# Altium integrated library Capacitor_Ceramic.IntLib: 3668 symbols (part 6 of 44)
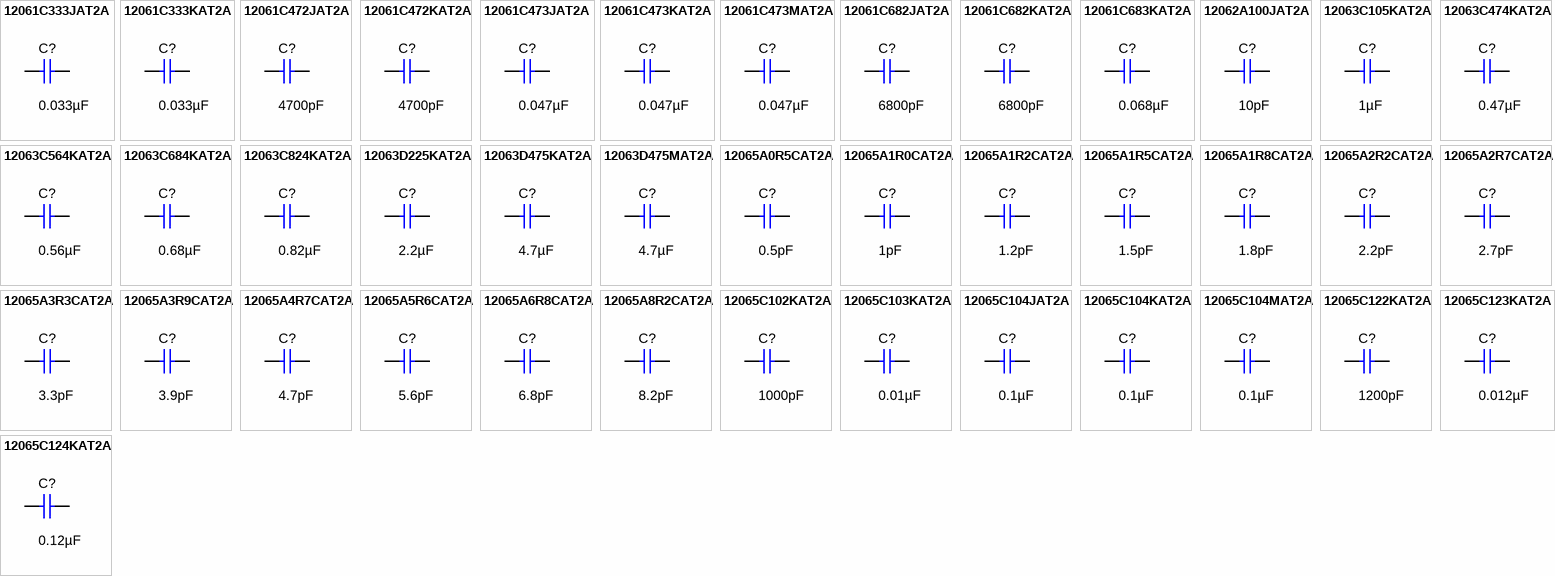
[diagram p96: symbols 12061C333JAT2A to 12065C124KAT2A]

## 12065C104KAT2A
designator C?  ValueDisplayed: 0.1µF  (hidden comment: 12065C104KAT2A)
CAP, CERM, 0.1 µF, 50 V,+/- 10%, X7R, 1206; Manufacturer: AVX; Polarized: N; CompType: Capacitor; Value: 0.1uF; U/M: EA; Cap_F: 0.0000001; Tolerance_%: 10; ESR_ohm: 0.037; Value1: 0.037 ohm; VDC_V: 50; Value2: 50V; TaMin_C: -55; TaMax_C: 125; Cap_Case: 1206; SizeArea_mm2: 5.12; SizeAreaWB_mm2: 10.92; SizeX_mm: 3.2; SizeY_mm: 1.6; SizeZ_mm: 1.35; AEC Category: Q200; Green_Lifecycle: Active; Green_REACh: Passed
signal-integrity model Cap
simulation model Cap
footprint 1206
footprint 1206M
footprint 1206L
pins: 1, 2

## 12065C104MAT2A
designator C?  ValueDisplayed: 0.1µF  (hidden comment: 12065C104MAT2A)
CAP, CERM, 0.1 µF, 50 V,+/- 20%, X7R, 1206; Manufacturer: AVX; Polarized: N; CompType: Capacitor; Value: 0.1uF; U/M: EA; Cap_F: 0.0000001; Tolerance_%: 20; ESR_ohm: 0.037; Value1: 0.037 ohm; VDC_V: 50; Value2: 50V; TaMin_C: -55; TaMax_C: 125; Cap_Case: 1206; SizeArea_mm2: 5.12; SizeAreaWB_mm2: 10.92; SizeX_mm: 3.2; SizeY_mm: 1.6; SizeZ_mm: 1.35; AEC Category: Q200; Green_Lifecycle: Active; Green_REACh: Passed
signal-integrity model Cap
simulation model Cap
footprint 1206
footprint 1206M
footprint 1206L
pins: 1, 2

## 12065C122KAT2A
designator C?  ValueDisplayed: 1200pF  (hidden comment: 12065C122KAT2A)
CAP, CERM, 1200 pF, 50 V,+/- 10%, X7R, 1206; Manufacturer: AVX; Polarized: N; CompType: Capacitor; Value: 1200pF; U/M: EA; Cap_F: 0.0000000012; Tolerance_%: 10; ESR_ohm: 0.385; Value1: 0.385 ohm; VDC_V: 50; Value2: 50V; TaMin_C: -55; TaMax_C: 125; Cap_Case: 1206; SizeArea_mm2: 5.12; SizeAreaWB_mm2: 10.92; SizeX_mm: 3.2; SizeY_mm: 1.6; SizeZ_mm: 1.35; AEC Category: Q200; Green_Lifecycle: Not Set; Green_REACh: Incomplete
signal-integrity model Cap
simulation model Cap
footprint 1206
footprint 1206M
footprint 1206L
pins: 1, 2

## 12065C123KAT2A
designator C?  ValueDisplayed: 0.012µF  (hidden comment: 12065C123KAT2A)
CAP, CERM, 0.012 µF, 50 V,+/- 10%, X7R, 1206; Manufacturer: AVX; Polarized: N; CompType: Capacitor; Value: 0.012uF; U/M: EA; Cap_F: 0.000000012; Tolerance_%: 10; ESR_ohm: 0.108; Value1: 0.108 ohm; VDC_V: 50; Value2: 50V; TaMin_C: -55; TaMax_C: 125; Cap_Case: 1206; SizeArea_mm2: 5.12; SizeAreaWB_mm2: 10.92; SizeX_mm: 3.2; SizeY_mm: 1.6; SizeZ_mm: 1.35; AEC Category: Q200; Green_Lifecycle: Not Set; Green_REACh: Incomplete
signal-integrity model Cap
simulation model Cap
footprint 1206
footprint 1206M
footprint 1206L
pins: 1, 2

## 12065C124KAT2A
designator C?  ValueDisplayed: 0.12µF  (hidden comment: 12065C124KAT2A)
CAP, CERM, 0.12 µF, 50 V,+/- 10%, X7R, 1206; Manufacturer: AVX; Polarized: N; CompType: Capacitor; Value: 0.12uF; U/M: EA; Cap_F: 0.00000012; Tolerance_%: 10; ESR_ohm: 0.034; Value1: 0.034 ohm; VDC_V: 50; Value2: 50V; TaMin_C: -55; TaMax_C: 125; Cap_Case: 1206; SizeArea_mm2: 5.12; SizeAreaWB_mm2: 10.92; SizeX_mm: 3.2; SizeY_mm: 1.6; SizeZ_mm: 1.35; AEC Category: Q200; Green_Lifecycle: Not Set; Green_REACh: Incomplete
signal-integrity model Cap
simulation model Cap
footprint 1206
footprint 1206M
footprint 1206L
pins: 1, 2

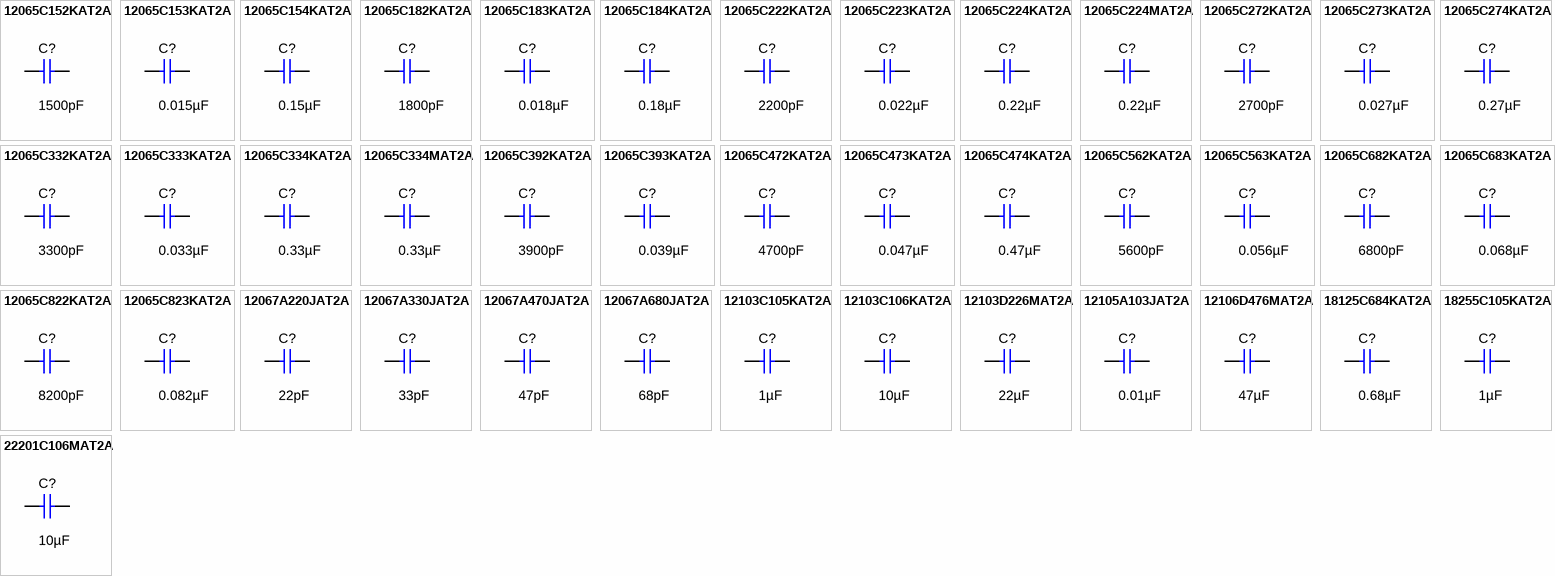
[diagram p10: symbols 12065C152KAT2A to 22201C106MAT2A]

## 12065C152KAT2A
designator C?  ValueDisplayed: 1500pF  (hidden comment: 12065C152KAT2A)
CAP, CERM, 1500 pF, 50 V,+/- 10%, X7R, 1206; Manufacturer: AVX; Polarized: N; CompType: Capacitor; Value: 1500pF; U/M: EA; Cap_F: 0.0000000015; Tolerance_%: 10; ESR_ohm: 0.338; Value1: 0.338 ohm; VDC_V: 50; Value2: 50V; TaMin_C: -55; TaMax_C: 125; Cap_Case: 1206; SizeArea_mm2: 5.12; SizeAreaWB_mm2: 10.92; SizeX_mm: 3.2; SizeY_mm: 1.6; SizeZ_mm: 1.35; AEC Category: Q200; Green_Lifecycle: Not Set; Green_REACh: Incomplete
signal-integrity model Cap
simulation model Cap
footprint 1206
footprint 1206M
footprint 1206L
pins: 1, 2

## 12065C153KAT2A
designator C?  ValueDisplayed: 0.015µF  (hidden comment: 12065C153KAT2A)
CAP, CERM, 0.015 µF, 50 V,+/- 10%, X7R, 1206; Manufacturer: AVX; Polarized: N; CompType: Capacitor; Value: 0.015uF; U/M: EA; Cap_F: 0.000000015; Tolerance_%: 10; ESR_ohm: 0.096; Value1: 0.096 ohm; VDC_V: 50; Value2: 50V; TaMin_C: -55; TaMax_C: 125; Cap_Case: 1206; SizeArea_mm2: 5.12; SizeAreaWB_mm2: 10.92; SizeX_mm: 3.2; SizeY_mm: 1.6; SizeZ_mm: 1.35; AEC Category: Q200; Green_Lifecycle: Not Set; Green_REACh: Incomplete
signal-integrity model Cap
simulation model Cap
footprint 1206
footprint 1206M
footprint 1206L
pins: 1, 2

## 12065C154KAT2A
designator C?  ValueDisplayed: 0.15µF  (hidden comment: 12065C154KAT2A)
CAP, CERM, 0.15 µF, 50 V,+/- 10%, X7R, 1206; Manufacturer: AVX; Polarized: N; CompType: Capacitor; Value: 0.15uF; U/M: EA; Cap_F: 0.00000015; Tolerance_%: 10; ESR_ohm: 0.03; Value1: 0.03 ohm; VDC_V: 50; Value2: 50V; TaMin_C: -55; TaMax_C: 125; Cap_Case: 1206; SizeArea_mm2: 5.12; SizeAreaWB_mm2: 10.92; SizeX_mm: 3.2; SizeY_mm: 1.6; SizeZ_mm: 1.35; AEC Category: Q200; Green_Lifecycle: Not Set; Green_REACh: Incomplete
signal-integrity model Cap
simulation model Cap
footprint 1206
footprint 1206M
footprint 1206L
pins: 1, 2

## 12065C182KAT2A
designator C?  ValueDisplayed: 1800pF  (hidden comment: 12065C182KAT2A)
CAP, CERM, 1800 pF, 50 V,+/- 10%, X7R, 1206; Manufacturer: AVX; Polarized: N; CompType: Capacitor; Value: 1800pF; U/M: EA; Cap_F: 0.0000000018; Tolerance_%: 10; ESR_ohm: 0.305; Value1: 0.305 ohm; VDC_V: 50; Value2: 50V; TaMin_C: -55; TaMax_C: 125; Cap_Case: 1206; SizeArea_mm2: 5.12; SizeAreaWB_mm2: 10.92; SizeX_mm: 3.2; SizeY_mm: 1.6; SizeZ_mm: 1.35; AEC Category: Q200; Green_Lifecycle: Not Set; Green_REACh: Incomplete
signal-integrity model Cap
simulation model Cap
footprint 1206
footprint 1206M
footprint 1206L
pins: 1, 2

## 12065C183KAT2A
designator C?  ValueDisplayed: 0.018µF  (hidden comment: 12065C183KAT2A)
CAP, CERM, 0.018 µF, 50 V,+/- 10%, X7R, 1206; Manufacturer: AVX; Polarized: N; CompType: Capacitor; Value: 0.018uF; U/M: EA; Cap_F: 0.000000018; Tolerance_%: 10; ESR_ohm: 0.087; Value1: 0.087 ohm; VDC_V: 50; Value2: 50V; TaMin_C: -55; TaMax_C: 125; Cap_Case: 1206; SizeArea_mm2: 5.12; SizeAreaWB_mm2: 10.92; SizeX_mm: 3.2; SizeY_mm: 1.6; SizeZ_mm: 1.35; AEC Category: Q200; Green_Lifecycle: Not Set; Green_REACh: Incomplete
signal-integrity model Cap
simulation model Cap
footprint 1206
footprint 1206M
footprint 1206L
pins: 1, 2

## 12065C184KAT2A
designator C?  ValueDisplayed: 0.18µF  (hidden comment: 12065C184KAT2A)
CAP, CERM, 0.18 µF, 50 V,+/- 10%, X7R, 1206; Manufacturer: AVX; Polarized: N; CompType: Capacitor; Value: 0.18uF; U/M: EA; Cap_F: 0.00000018; Tolerance_%: 10; ESR_ohm: 0.028; Value1: 0.028 ohm; VDC_V: 50; Value2: 50V; TaMin_C: -55; TaMax_C: 125; Cap_Case: 1206; SizeArea_mm2: 5.12; SizeAreaWB_mm2: 10.92; SizeX_mm: 3.2; SizeY_mm: 1.6; SizeZ_mm: 1.35; AEC Category: Q200; Green_Lifecycle: Not Set; Green_REACh: Incomplete
signal-integrity model Cap
simulation model Cap
footprint 1206
footprint 1206M
footprint 1206L
pins: 1, 2

## 12065C222KAT2A
designator C?  ValueDisplayed: 2200pF  (hidden comment: 12065C222KAT2A)
CAP, CERM, 2200 pF, 50 V,+/- 10%, X7R, 1206; Manufacturer: AVX; Polarized: N; CompType: Capacitor; Value: 2200pF; U/M: EA; Cap_F: 0.0000000022; Tolerance_%: 10; ESR_ohm: 0.272; Value1: 0.272 ohm; VDC_V: 50; Value2: 50V; TaMin_C: -55; TaMax_C: 125; Cap_Case: 1206; SizeArea_mm2: 5.12; SizeAreaWB_mm2: 10.92; SizeX_mm: 3.2; SizeY_mm: 1.6; SizeZ_mm: 1.35; AEC Category: Q200; Green_Lifecycle: Not Set; Green_REACh: Incomplete
signal-integrity model Cap
simulation model Cap
footprint 1206
footprint 1206M
footprint 1206L
pins: 1, 2

## 12065C223KAT2A
designator C?  ValueDisplayed: 0.022µF  (hidden comment: 12065C223KAT2A)
CAP, CERM, 0.022 µF, 50 V,+/- 10%, X7R, 1206; Manufacturer: AVX; Polarized: N; CompType: Capacitor; Value: 0.022uF; U/M: EA; Cap_F: 0.000000022; Tolerance_%: 10; ESR_ohm: 0.079; Value1: 0.079 ohm; VDC_V: 50; Value2: 50V; TaMin_C: -55; TaMax_C: 125; Cap_Case: 1206; SizeArea_mm2: 5.12; SizeAreaWB_mm2: 10.92; SizeX_mm: 3.2; SizeY_mm: 1.6; SizeZ_mm: 1.35; AEC Category: Q200; Green_Lifecycle: Not Set; Green_REACh: Incomplete
signal-integrity model Cap
simulation model Cap
footprint 1206
footprint 1206M
footprint 1206L
pins: 1, 2

## 12065C224KAT2A
designator C?  ValueDisplayed: 0.22µF  (hidden comment: 12065C224KAT2A)
CAP, CERM, 0.22 µF, 50 V,+/- 10%, X7R, 1206; Manufacturer: AVX; Polarized: N; CompType: Capacitor; Value: 0.22uF; U/M: EA; Cap_F: 0.00000022; Tolerance_%: 10; ESR_ohm: 0.026; Value1: 0.026 ohm; VDC_V: 50; Value2: 50V; TaMin_C: -55; TaMax_C: 125; Cap_Case: 1206; SizeArea_mm2: 5.12; SizeAreaWB_mm2: 10.92; SizeX_mm: 3.2; SizeY_mm: 1.6; SizeZ_mm: 1.35; AEC Category: Q200; Green_Lifecycle: Not Set; Green_REACh: Incomplete
signal-integrity model Cap
simulation model Cap
footprint 1206
footprint 1206M
footprint 1206L
pins: 1, 2

## 12065C224MAT2A
designator C?  ValueDisplayed: 0.22µF  (hidden comment: 12065C224MAT2A)
CAP, CERM, 0.22 µF, 50 V,+/- 20%, X7R, 1206; Manufacturer: AVX; Polarized: N; CompType: Capacitor; Value: 0.22uF; U/M: EA; Cap_F: 0.00000022; Tolerance_%: 20; ESR_ohm: 0.026; Value1: 0.026 ohm; VDC_V: 50; Value2: 50V; TaMin_C: -55; TaMax_C: 125; Cap_Case: 1206; SizeArea_mm2: 5.12; SizeAreaWB_mm2: 10.92; SizeX_mm: 3.2; SizeY_mm: 1.6; SizeZ_mm: 1.35; AEC Category: Q200; Green_Lifecycle: Not Set; Green_REACh: Incomplete
signal-integrity model Cap
simulation model Cap
footprint 1206
footprint 1206M
footprint 1206L
pins: 1, 2

## 12065C272KAT2A
designator C?  ValueDisplayed: 2700pF  (hidden comment: 12065C272KAT2A)
CAP, CERM, 2700 pF, 50 V,+/- 10%, X7R, 1206; Manufacturer: AVX; Polarized: N; CompType: Capacitor; Value: 2700pF; U/M: EA; Cap_F: 0.0000000027; Tolerance_%: 10; ESR_ohm: 0.242; Value1: 0.242 ohm; VDC_V: 50; Value2: 50V; TaMin_C: -55; TaMax_C: 125; Cap_Case: 1206; SizeArea_mm2: 5.12; SizeAreaWB_mm2: 10.92; SizeX_mm: 3.2; SizeY_mm: 1.6; SizeZ_mm: 1.35; AEC Category: Q200; Green_Lifecycle: Not Set; Green_REACh: Incomplete
signal-integrity model Cap
simulation model Cap
footprint 1206
footprint 1206M
footprint 1206L
pins: 1, 2

## 12065C273KAT2A
designator C?  ValueDisplayed: 0.027µF  (hidden comment: 12065C273KAT2A)
CAP, CERM, 0.027 µF, 50 V,+/- 10%, X7R, 1206; Manufacturer: AVX; Polarized: N; CompType: Capacitor; Value: 0.027uF; U/M: EA; Cap_F: 0.000000027; Tolerance_%: 10; ESR_ohm: 0.071; Value1: 0.071 ohm; VDC_V: 50; Value2: 50V; TaMin_C: -55; TaMax_C: 125; Cap_Case: 1206; SizeArea_mm2: 5.12; SizeAreaWB_mm2: 10.92; SizeX_mm: 3.2; SizeY_mm: 1.6; SizeZ_mm: 1.35; AEC Category: Q200; Green_Lifecycle: Not Set; Green_REACh: Incomplete
signal-integrity model Cap
simulation model Cap
footprint 1206
footprint 1206M
footprint 1206L
pins: 1, 2

## 12065C274KAT2A
designator C?  ValueDisplayed: 0.27µF  (hidden comment: 12065C274KAT2A)
CAP, CERM, 0.27 µF, 50 V,+/- 10%, X7R, 1206; Manufacturer: AVX; Polarized: N; CompType: Capacitor; Value: 0.27uF; U/M: EA; Cap_F: 0.00000027; Tolerance_%: 10; ESR_ohm: 0.023; Value1: 0.023 ohm; VDC_V: 50; Value2: 50V; TaMin_C: -55; TaMax_C: 125; Cap_Case: 1206; SizeArea_mm2: 5.12; SizeAreaWB_mm2: 10.92; SizeX_mm: 3.2; SizeY_mm: 1.6; SizeZ_mm: 1.35; AEC Category: Q200; Green_Lifecycle: Not Set; Green_REACh: Incomplete
signal-integrity model Cap
simulation model Cap
footprint 1206
footprint 1206M
footprint 1206L
pins: 1, 2

## 12065C332KAT2A
designator C?  ValueDisplayed: 3300pF  (hidden comment: 12065C332KAT2A)
CAP, CERM, 3300 pF, 50 V,+/- 10%, X7R, 1206; Manufacturer: AVX; Polarized: N; CompType: Capacitor; Value: 3300pF; U/M: EA; Cap_F: 0.0000000033; Tolerance_%: 10; ESR_ohm: 0.216; Value1: 0.216 ohm; VDC_V: 50; Value2: 50V; TaMin_C: -55; TaMax_C: 125; Cap_Case: 1206; SizeArea_mm2: 5.12; SizeAreaWB_mm2: 10.92; SizeX_mm: 3.2; SizeY_mm: 1.6; SizeZ_mm: 1.35; AEC Category: Q200; Green_Lifecycle: Not Set; Green_REACh: Incomplete
signal-integrity model Cap
simulation model Cap
footprint 1206
footprint 1206M
footprint 1206L
pins: 1, 2

## 12065C333KAT2A
designator C?  ValueDisplayed: 0.033µF  (hidden comment: 12065C333KAT2A)
CAP, CERM, 0.033 µF, 50 V,+/- 10%, X7R, 1206; Manufacturer: AVX; Polarized: N; CompType: Capacitor; Value: 0.033uF; U/M: EA; Cap_F: 0.000000033; Tolerance_%: 10; ESR_ohm: 0.064; Value1: 0.064 ohm; VDC_V: 50; Value2: 50V; TaMin_C: -55; TaMax_C: 125; Cap_Case: 1206; SizeArea_mm2: 5.12; SizeAreaWB_mm2: 10.92; SizeX_mm: 3.2; SizeY_mm: 1.6; SizeZ_mm: 1.35; AEC Category: Q200; Green_Lifecycle: Not Set; Green_REACh: Incomplete
signal-integrity model Cap
simulation model Cap
footprint 1206
footprint 1206M
footprint 1206L
pins: 1, 2

## 12065C334KAT2A
designator C?  ValueDisplayed: 0.33µF  (hidden comment: 12065C334KAT2A)
CAP, CERM, 0.33 µF, 50 V,+/- 10%, X7R, 1206; Manufacturer: AVX; Polarized: N; CompType: Capacitor; Value: 0.33uF; U/M: EA; Cap_F: 0.00000033; Tolerance_%: 10; ESR_ohm: 0.021; Value1: 0.021 ohm; VDC_V: 50; Value2: 50V; TaMin_C: -55; TaMax_C: 125; Cap_Case: 1206; SizeArea_mm2: 5.12; SizeAreaWB_mm2: 10.92; SizeX_mm: 3.2; SizeY_mm: 1.6; SizeZ_mm: 1.35; AEC Category: Q200; Green_Lifecycle: Not Set; Green_REACh: Incomplete
signal-integrity model Cap
simulation model Cap
footprint 1206
footprint 1206M
footprint 1206L
pins: 1, 2

## 12065C334MAT2A
designator C?  ValueDisplayed: 0.33µF  (hidden comment: 12065C334MAT2A)
CAP, CERM, 0.33 µF, 50 V,+/- 20%, X7R, 1206; Manufacturer: AVX; Polarized: N; CompType: Capacitor; Value: 0.33uF; U/M: EA; Cap_F: 0.00000033; Tolerance_%: 20; ESR_ohm: 0.021; Value1: 0.021 ohm; VDC_V: 50; Value2: 50V; TaMin_C: -55; TaMax_C: 125; Cap_Case: 1206; SizeArea_mm2: 5.12; SizeAreaWB_mm2: 10.92; SizeX_mm: 3.2; SizeY_mm: 1.6; SizeZ_mm: 1.35; AEC Category: Q200; Green_Lifecycle: Not Set; Green_REACh: Incomplete
signal-integrity model Cap
simulation model Cap
footprint 1206
footprint 1206M
footprint 1206L
pins: 1, 2

## 12065C392KAT2A
designator C?  ValueDisplayed: 3900pF  (hidden comment: 12065C392KAT2A)
CAP, CERM, 3900 pF, 50 V,+/- 10%, X7R, 1206; Manufacturer: AVX; Polarized: N; CompType: Capacitor; Value: 3900pF; U/M: EA; Cap_F: 0.0000000039; Tolerance_%: 10; ESR_ohm: 0.196; Value1: 0.196 ohm; VDC_V: 50; Value2: 50V; TaMin_C: -55; TaMax_C: 125; Cap_Case: 1206; SizeArea_mm2: 5.12; SizeAreaWB_mm2: 10.92; SizeX_mm: 3.2; SizeY_mm: 1.6; SizeZ_mm: 1.35; AEC Category: Q200; Green_Lifecycle: Not Set; Green_REACh: Incomplete
signal-integrity model Cap
simulation model Cap
footprint 1206
footprint 1206M
footprint 1206L
pins: 1, 2

## 12065C393KAT2A
designator C?  ValueDisplayed: 0.039µF  (hidden comment: 12065C393KAT2A)
CAP, CERM, 0.039 µF, 50 V,+/- 10%, X7R, 1206; Manufacturer: AVX; Polarized: N; CompType: Capacitor; Value: 0.039uF; U/M: EA; Cap_F: 0.000000039; Tolerance_%: 10; ESR_ohm: 0.059; Value1: 0.059 ohm; VDC_V: 50; Value2: 50V; TaMin_C: -55; TaMax_C: 125; Cap_Case: 1206; SizeArea_mm2: 5.12; SizeAreaWB_mm2: 10.92; SizeX_mm: 3.2; SizeY_mm: 1.6; SizeZ_mm: 1.35; AEC Category: Q200; Green_Lifecycle: Not Set; Green_REACh: Incomplete
signal-integrity model Cap
simulation model Cap
footprint 1206
footprint 1206M
footprint 1206L
pins: 1, 2

## 12065C472KAT2A
designator C?  ValueDisplayed: 4700pF  (hidden comment: 12065C472KAT2A)
CAP, CERM, 4700 pF, 50 V,+/- 10%, X7R, 1206; Manufacturer: AVX; Polarized: N; CompType: Capacitor; Value: 4700pF; U/M: EA; Cap_F: 0.0000000047; Tolerance_%: 10; ESR_ohm: 0.178; Value1: 0.178 ohm; VDC_V: 50; Value2: 50V; TaMin_C: -55; TaMax_C: 125; Cap_Case: 1206; SizeArea_mm2: 5.12; SizeAreaWB_mm2: 10.92; SizeX_mm: 3.2; SizeY_mm: 1.6; SizeZ_mm: 1.35; AEC Category: Q200; Green_Lifecycle: Not Set; Green_REACh: Incomplete
signal-integrity model Cap
simulation model Cap
footprint 1206
footprint 1206M
footprint 1206L
pins: 1, 2

## 12065C473KAT2A
designator C?  ValueDisplayed: 0.047µF  (hidden comment: 12065C473KAT2A)
CAP, CERM, 0.047 µF, 50 V,+/- 10%, X7R, 1206; Manufacturer: AVX; Polarized: N; CompType: Capacitor; Value: 0.047uF; U/M: EA; Cap_F: 0.000000047; Tolerance_%: 10; ESR_ohm: 0.054; Value1: 0.054 ohm; VDC_V: 50; Value2: 50V; TaMin_C: -55; TaMax_C: 125; Cap_Case: 1206; SizeArea_mm2: 5.12; SizeAreaWB_mm2: 10.92; SizeX_mm: 3.2; SizeY_mm: 1.6; SizeZ_mm: 1.35; AEC Category: Q200; Green_Lifecycle: Not Set; Green_REACh: Incomplete
signal-integrity model Cap
simulation model Cap
footprint 1206
footprint 1206M
footprint 1206L
pins: 1, 2

## 12065C474KAT2A
designator C?  ValueDisplayed: 0.47µF  (hidden comment: 12065C474KAT2A)
CAP, CERM, 0.47 µF, 50 V,+/- 10%, X7R, 1206; Manufacturer: AVX; Polarized: N; CompType: Capacitor; Value: 0.47uF; U/M: EA; Cap_F: 0.00000047; Tolerance_%: 10; ESR_ohm: 0.018; Value1: 0.018 ohm; VDC_V: 50; Value2: 50V; TaMin_C: -55; TaMax_C: 125; Cap_Case: 1206; SizeArea_mm2: 5.12; SizeAreaWB_mm2: 10.92; SizeX_mm: 3.2; SizeY_mm: 1.6; SizeZ_mm: 1.35; AEC Category: Q200; Green_Lifecycle: Active; Green_REACh: Passed
signal-integrity model Cap
simulation model Cap
footprint 1206
footprint 1206M
footprint 1206L
pins: 1, 2

## 12065C562KAT2A
designator C?  ValueDisplayed: 5600pF  (hidden comment: 12065C562KAT2A)
CAP, CERM, 5600 pF, 50 V,+/- 10%, X7R, 1206; Manufacturer: AVX; Polarized: N; CompType: Capacitor; Value: 5600pF; U/M: EA; Cap_F: 0.0000000056; Tolerance_%: 10; ESR_ohm: 0.162; Value1: 0.162 ohm; VDC_V: 50; Value2: 50V; TaMin_C: -55; TaMax_C: 125; Cap_Case: 1206; SizeArea_mm2: 5.12; SizeAreaWB_mm2: 10.92; SizeX_mm: 3.2; SizeY_mm: 1.6; SizeZ_mm: 1.35; AEC Category: Q200; Green_Lifecycle: Not Set; Green_REACh: Incomplete
signal-integrity model Cap
simulation model Cap
footprint 1206
footprint 1206M
footprint 1206L
pins: 1, 2

## 12065C563KAT2A
designator C?  ValueDisplayed: 0.056µF  (hidden comment: 12065C563KAT2A)
CAP, CERM, 0.056 µF, 50 V,+/- 10%, X7R, 1206; Manufacturer: AVX; Polarized: N; CompType: Capacitor; Value: 0.056uF; U/M: EA; Cap_F: 0.000000056; Tolerance_%: 10; ESR_ohm: 0.049; Value1: 0.049 ohm; VDC_V: 50; Value2: 50V; TaMin_C: -55; TaMax_C: 125; Cap_Case: 1206; SizeArea_mm2: 5.12; SizeAreaWB_mm2: 10.92; SizeX_mm: 3.2; SizeY_mm: 1.6; SizeZ_mm: 1.35; AEC Category: Q200; Green_Lifecycle: Not Set; Green_REACh: Incomplete
signal-integrity model Cap
simulation model Cap
footprint 1206
footprint 1206M
footprint 1206L
pins: 1, 2

## 12065C682KAT2A
designator C?  ValueDisplayed: 6800pF  (hidden comment: 12065C682KAT2A)
CAP, CERM, 6800 pF, 50 V,+/- 10%, X7R, 1206; Manufacturer: AVX; Polarized: N; CompType: Capacitor; Value: 6800pF; U/M: EA; Cap_F: 0.0000000068; Tolerance_%: 10; ESR_ohm: 0.146; Value1: 0.146 ohm; VDC_V: 50; Value2: 50V; TaMin_C: -55; TaMax_C: 125; Cap_Case: 1206; SizeArea_mm2: 5.12; SizeAreaWB_mm2: 10.92; SizeX_mm: 3.2; SizeY_mm: 1.6; SizeZ_mm: 1.35; AEC Category: Q200; Green_Lifecycle: Not Set; Green_REACh: Incomplete
signal-integrity model Cap
simulation model Cap
footprint 1206
footprint 1206M
footprint 1206L
pins: 1, 2

## 12065C683KAT2A
designator C?  ValueDisplayed: 0.068µF  (hidden comment: 12065C683KAT2A)
CAP, CERM, 0.068 µF, 50 V,+/- 10%, X7R, 1206; Manufacturer: AVX; Polarized: N; CompType: Capacitor; Value: 0.068uF; U/M: EA; Cap_F: 0.000000068; Tolerance_%: 10; ESR_ohm: 0.045; Value1: 0.045 ohm; VDC_V: 50; Value2: 50V; TaMin_C: -55; TaMax_C: 125; Cap_Case: 1206; SizeArea_mm2: 5.12; SizeAreaWB_mm2: 10.92; SizeX_mm: 3.2; SizeY_mm: 1.6; SizeZ_mm: 1.35; AEC Category: Q200; Green_Lifecycle: Not Set; Green_REACh: Incomplete
signal-integrity model Cap
simulation model Cap
footprint 1206
footprint 1206M
footprint 1206L
pins: 1, 2

## 12065C822KAT2A
designator C?  ValueDisplayed: 8200pF  (hidden comment: 12065C822KAT2A)
CAP, CERM, 8200 pF, 50 V,+/- 10%, X7R, 1206; Manufacturer: AVX; Polarized: N; CompType: Capacitor; Value: 8200pF; U/M: EA; Cap_F: 0.0000000082; Tolerance_%: 10; ESR_ohm: 0.132; Value1: 0.132 ohm; VDC_V: 50; Value2: 50V; TaMin_C: -55; TaMax_C: 125; Cap_Case: 1206; SizeArea_mm2: 5.12; SizeAreaWB_mm2: 10.92; SizeX_mm: 3.2; SizeY_mm: 1.6; SizeZ_mm: 1.35; AEC Category: Q200; Green_Lifecycle: Not Set; Green_REACh: Incomplete
signal-integrity model Cap
simulation model Cap
footprint 1206
footprint 1206M
footprint 1206L
pins: 1, 2

## 12065C823KAT2A
designator C?  ValueDisplayed: 0.082µF  (hidden comment: 12065C823KAT2A)
CAP, CERM, 0.082 µF, 50 V,+/- 10%, X7R, 1206; Manufacturer: AVX; Polarized: N; CompType: Capacitor; Value: 0.082uF; U/M: EA; Cap_F: 0.000000082; Tolerance_%: 10; ESR_ohm: 0.041; Value1: 0.041 ohm; VDC_V: 50; Value2: 50V; TaMin_C: -55; TaMax_C: 125; Cap_Case: 1206; SizeArea_mm2: 5.12; SizeAreaWB_mm2: 10.92; SizeX_mm: 3.2; SizeY_mm: 1.6; SizeZ_mm: 1.35; AEC Category: Q200; Green_Lifecycle: Not Set; Green_REACh: Incomplete
signal-integrity model Cap
simulation model Cap
footprint 1206
footprint 1206M
footprint 1206L
pins: 1, 2

## 12067A220JAT2A
designator C?  ValueDisplayed: 22pF  (hidden comment: 12067A220JAT2A)
CAP, CERM, 22 pF, 500 V,+/- 5%, C0G/NP0, 1206; Manufacturer: AVX; Polarized: N; CompType: Capacitor; Value: 22pF; U/M: EA; Cap_F: 0.000000000022; Tolerance_%: 5; VDC_V: 500; Value2: 500V; TaMin_C: -55; TaMax_C: 125; Cap_Case: 1206; SizeArea_mm2: 5.12; SizeAreaWB_mm2: 10.92; SizeX_mm: 3.2; SizeY_mm: 1.6; SizeZ_mm: 1.35; AEC Category: Q200; Green_Lifecycle: Not Set; Green_REACh: Incomplete
signal-integrity model Cap
simulation model Cap
footprint 1206
footprint 1206M
footprint 1206L
pins: 1, 2

## 12067A330JAT2A
designator C?  ValueDisplayed: 33pF  (hidden comment: 12067A330JAT2A)
CAP, CERM, 33 pF, 500 V,+/- 5%, C0G/NP0, 1206; Manufacturer: AVX; Polarized: N; CompType: Capacitor; Value: 33pF; U/M: EA; Cap_F: 0.000000000033; Tolerance_%: 5; VDC_V: 500; Value2: 500V; TaMin_C: -55; TaMax_C: 125; Cap_Case: 1206; SizeArea_mm2: 5.12; SizeAreaWB_mm2: 10.92; SizeX_mm: 3.2; SizeY_mm: 1.6; SizeZ_mm: 1.35; AEC Category: Q200; Green_Lifecycle: Not Set; Green_REACh: Incomplete
signal-integrity model Cap
simulation model Cap
footprint 1206
footprint 1206M
footprint 1206L
pins: 1, 2

## 12067A470JAT2A
designator C?  ValueDisplayed: 47pF  (hidden comment: 12067A470JAT2A)
CAP, CERM, 47 pF, 500 V,+/- 5%, C0G/NP0, 1206; Manufacturer: AVX; Polarized: N; CompType: Capacitor; Value: 47pF; U/M: EA; Cap_F: 0.000000000047; Tolerance_%: 5; VDC_V: 500; Value2: 500V; TaMin_C: -55; TaMax_C: 125; Cap_Case: 1206; SizeArea_mm2: 5.12; SizeAreaWB_mm2: 10.92; SizeX_mm: 3.2; SizeY_mm: 1.6; SizeZ_mm: 1.35; AEC Category: Q200; Green_Lifecycle: Not Set; Green_REACh: Incomplete
signal-integrity model Cap
simulation model Cap
footprint 1206
footprint 1206M
footprint 1206L
pins: 1, 2

## 12067A680JAT2A
designator C?  ValueDisplayed: 68pF  (hidden comment: 12067A680JAT2A)
CAP, CERM, 68 pF, 500 V,+/- 5%, C0G/NP0, 1206; Manufacturer: AVX; Polarized: N; CompType: Capacitor; Value: 68pF; U/M: EA; Cap_F: 0.000000000068; Tolerance_%: 5; VDC_V: 500; Value2: 500V; TaMin_C: -55; TaMax_C: 125; Cap_Case: 1206; SizeArea_mm2: 5.12; SizeAreaWB_mm2: 10.92; SizeX_mm: 3.2; SizeY_mm: 1.6; SizeZ_mm: 1.35; AEC Category: Q200; Green_Lifecycle: Not Set; Green_REACh: Incomplete
signal-integrity model Cap
simulation model Cap
footprint 1206
footprint 1206M
footprint 1206L
pins: 1, 2

## 12103C105KAT2A
designator C?  ValueDisplayed: 1µF  (hidden comment: 12103C105KAT2A)
CAP, CERM, 1 µF, 25 V,+/- 10%, X7R, 1210; Manufacturer: AVX; Polarized: N; CompType: Capacitor; Value: 1uF; U/M: EA; Cap_F: 0.000001; Tolerance_%: 10; VDC_V: 25; Value2: 25V; TaMin_C: -55; TaMax_C: 125; Cap_Case: 1210; SizeArea_mm2: 8; SizeAreaWB_mm2: 14.7; SizeX_mm: 3.2; SizeY_mm: 2.5; SizeZ_mm: 1.5; AEC Category: Q200; Green_Lifecycle: Active; Green_REACh: Passed
signal-integrity model Cap
simulation model Cap
footprint 1210_150
footprint 1210_150M
footprint 1210_150L
pins: 1, 2

## 12103C106KAT2A
designator C?  ValueDisplayed: 10µF  (hidden comment: 12103C106KAT2A)
CAP, CERM, 10 µF, 25 V,+/- 10%, X7R, 1210; Manufacturer: AVX; Polarized: N; CompType: Capacitor; Value: 10uF; U/M: EA; Cap_F: 0.00001; Tolerance_%: 10; VDC_V: 25; Value2: 25V; TaMin_C: -55; TaMax_C: 125; Cap_Case: 1210; SizeArea_mm2: 8; SizeAreaWB_mm2: 14.7; SizeX_mm: 3.2; SizeY_mm: 2.5; SizeZ_mm: 2.8; AEC Category: Q200; Green_Lifecycle: Active; Green_REACh: Passed
signal-integrity model Cap
simulation model Cap
footprint 1210_280
pins: 1, 2

## 12103D226MAT2A
designator C?  ValueDisplayed: 22µF  (hidden comment: 12103D226MAT2A)
CAP, CERM, 22 µF, 25 V,+/- 20%, X5R, 1210; Manufacturer: AVX; Polarized: N; CompType: Capacitor; Value: 22uF; U/M: EA; Cap_F: 0.000022; Tolerance_%: 20; VDC_V: 25; Value2: 25V; TaMin_C: -55; TaMax_C: 85; Cap_Case: 1210; SizeArea_mm2: 8; SizeAreaWB_mm2: 14.7; SizeX_mm: 3.2; SizeY_mm: 2.5; SizeZ_mm: 2.8; AEC Category: Q200; Green_Lifecycle: Active; Green_REACh: Passed
signal-integrity model Cap
simulation model Cap
footprint 1210_280
pins: 1, 2

## 12105A103JAT2A
designator C?  ValueDisplayed: 0.01µF  (hidden comment: 12105A103JAT2A)
CAP, CERM, 0.01 µF, 50 V,+/- 5%, C0G/NP0, 1210; Manufacturer: AVX; Polarized: N; CompType: Capacitor; Value: 0.01uF; U/M: EA; Cap_F: 0.00000001; Tolerance_%: 5; VDC_V: 50; Value2: 50V; TaMin_C: -55; TaMax_C: 125; Cap_Case: 1210; SizeArea_mm2: 8; SizeAreaWB_mm2: 14.7; SizeX_mm: 3.2; SizeY_mm: 2.5; SizeZ_mm: 1.35; AEC Category: Q200; Green_Lifecycle: Active; Green_REACh: Passed
signal-integrity model Cap
simulation model Cap
footprint 1210
footprint 1210M
footprint 1210L
pins: 1, 2

## 12106D476MAT2A
designator C?  ValueDisplayed: 47µF  (hidden comment: 12106D476MAT2A)
CAP, CERM, 47 µF, 6.3 V,+/- 20%, X5R, 1210; Manufacturer: AVX; Polarized: N; CompType: Capacitor; Value: 47uF; U/M: EA; Cap_F: 0.000047; Tolerance_%: 20; VDC_V: 6.3; Value2: 6.3V; TaMin_C: -55; TaMax_C: 85; Cap_Case: 1210; SizeArea_mm2: 8; SizeAreaWB_mm2: 14.7; SizeX_mm: 3.2; SizeY_mm: 2.5; SizeZ_mm: 2.8; AEC Category: Q200; Green_Lifecycle: Not Set; Green_REACh: Incomplete
signal-integrity model Cap
simulation model Cap
footprint 1210_280
pins: 1, 2

## 18125C684KAT2A
designator C?  ValueDisplayed: 0.68µF  (hidden comment: 18125C684KAT2A)
CAP, CERM, 0.68 µF, 50 V,+/- 10%, X7R, 1812; Manufacturer: AVX; Polarized: N; CompType: Capacitor; Value: 0.68uF; U/M: EA; Cap_F: 0.00000068; Tolerance_%: 10; ESR_ohm: 0.028; Value1: 0.028 ohm; VDC_V: 50; Value2: 50V; TaMin_C: -55; TaMax_C: 125; Cap_Case: 1812; SizeArea_mm2: 14.4; SizeAreaWB_mm2: 23.1; SizeX_mm: 4.5; SizeY_mm: 3.2; SizeZ_mm: 1.35; AEC Category: Q200; Green_Lifecycle: Not Set; Green_REACh: Incomplete
signal-integrity model Cap
simulation model Cap
footprint 1812
footprint 1812M
footprint 1812L
footprint 1812_HV
pins: 1, 2

## 18255C105KAT2A
designator C?  ValueDisplayed: 1µF  (hidden comment: 18255C105KAT2A)
CAP, CERM, 1 µF, 50 V,+/- 10%, X7R, 1825; Manufacturer: AVX; Polarized: N; CompType: Capacitor; Value: 1uF; U/M: EA; Cap_F: 0.000001; Tolerance_%: 10; ESR_ohm: 0.024; Value1: 0.024 ohm; VDC_V: 50; Value2: 50V; TaMin_C: -55; TaMax_C: 125; Cap_Case: 1825; SizeArea_mm2: 28.8; SizeAreaWB_mm2: 54.6; SizeX_mm: 4.5; SizeY_mm: 6.4; SizeZ_mm: 1.1; AEC Category: Q200; Green_Lifecycle: Not Set; Green_REACh: Incomplete
signal-integrity model Cap
simulation model Cap
footprint 1825
footprint 1825_M
footprint 1825_L
pins: 1, 2

## 22201C106MAT2A
designator C?  ValueDisplayed: 10µF  (hidden comment: 22201C106MAT2A)
CAP, CERM, 10 µF, 100 V,+/- 20%, X7R, 2220; Manufacturer: AVX; Polarized: N; CompType: Capacitor; Value: 10uF; U/M: EA; Cap_F: 0.00001; Tolerance_%: 20; VDC_V: 100; Value2: 100V; TaMin_C: -55; TaMax_C: 125; Cap_Case: 2220; SizeArea_mm2: 28.5; SizeAreaWB_mm2: 53.9; SizeX_mm: 5.7; SizeY_mm: 5; SizeZ_mm: 2.8; AEC Category: Q200; Green_Lifecycle: Not Set; Green_REACh: Incomplete
signal-integrity model Cap
simulation model Cap
footprint 2220_280
footprint 2220_280M
footprint 2220_280L
pins: 1, 2

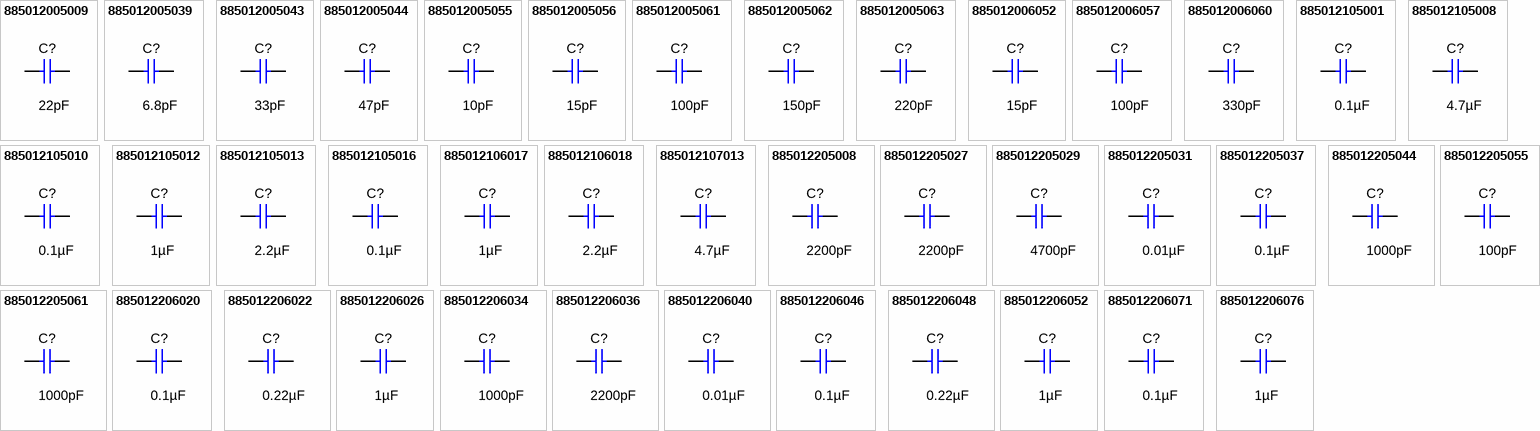
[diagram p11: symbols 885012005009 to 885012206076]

## 885012005009
designator C?  ValueDisplayed: 22pF  (hidden comment: 885012005009)
CAP, CERM, 22 pF, 10 V,+/- 5%, C0G/NP0, 0402; Manufacturer: Wurth Elektronik; Polarized: N; CompType: Capacitor; Value: 22pF; U/M: EA; Cap_F: 0.000000000022; Tolerance_%: 5; VDC_V: 10; Value2: 10V; TaMin_C: -55; TaMax_C: 125; Cap_Case: 0402; SizeArea_mm2: 0.5; SizeAreaWB_mm2: 3; SizeX_mm: 1; SizeZ_mm: 0.6; AEC Category: Q200
signal-integrity model Cap
simulation model Cap
footprint 0402
footprint 0402M
footprint 0402L
footprint 0402S
pins: 1, 2

## 885012005039
designator C?  ValueDisplayed: 6.8pF  (hidden comment: 885012005039)
CAP, CERM, 6.8 pF, 25 V,+/- 8%, C0G/NP0, 0402; Manufacturer: Wurth Elektronik; Polarized: N; CompType: Capacitor; Value: 6.8pF; U/M: EA; Cap_F: 0.0000000000068; Tolerance_%: 8; VDC_V: 25; Value2: 25V; TaMin_C: -55; TaMax_C: 125; Cap_Case: 0402; SizeArea_mm2: 0.5; SizeAreaWB_mm2: 3; SizeX_mm: 1; SizeZ_mm: 0.6; AEC Category: Q200; Green_Lifecycle: Not Set; Green_REACh: Incomplete
signal-integrity model Cap
simulation model Cap
footprint 0402
footprint 0402M
footprint 0402L
footprint 0402S
pins: 1, 2

## 885012005043
designator C?  ValueDisplayed: 33pF  (hidden comment: 885012005043)
CAP, CERM, 33 pF, 25 V,+/- 5%, C0G/NP0, 0402; Manufacturer: Wurth Elektronik; Polarized: N; CompType: Capacitor; Value: 33pF; U/M: EA; Cap_F: 0.000000000033; Tolerance_%: 5; VDC_V: 25; Value2: 25V; TaMin_C: -55; TaMax_C: 125; Cap_Case: 0402; SizeArea_mm2: 0.5; SizeAreaWB_mm2: 3; SizeX_mm: 1; SizeZ_mm: 0.6; AEC Category: Q200
signal-integrity model Cap
simulation model Cap
footprint 0402
footprint 0402M
footprint 0402L
footprint 0402S
pins: 1, 2

## 885012005044
designator C?  ValueDisplayed: 47pF  (hidden comment: 885012005044)
CAP, CERM, 47 pF, 50 V,+/- 5%, C0G/NP0, 0402; Manufacturer: Wurth Elektronik; Polarized: N; CompType: Capacitor; Value: 47pF; U/M: EA; Cap_F: 0.000000000047; Tolerance_%: 5; VDC_V: 50; Value2: 50V; TaMin_C: -55; TaMax_C: 125; Cap_Case: 0402; SizeArea_mm2: 0.5; SizeAreaWB_mm2: 3; SizeX_mm: 1; SizeZ_mm: 0.6; AEC Category: Q200; Green_Lifecycle: Not Set; Green_REACh: Incomplete
signal-integrity model Cap
simulation model Cap
footprint 0402
footprint 0402M
footprint 0402L
footprint 0402S
pins: 1, 2

## 885012005055
designator C?  ValueDisplayed: 10pF  (hidden comment: 885012005055)
CAP, CERM, 10 pF, 50 V,+/- 5%, C0G/NP0, 0402; Manufacturer: Wurth Elektronik; Polarized: N; CompType: Capacitor; Value: 10pF; U/M: EA; Cap_F: 0.00000000001; Tolerance_%: 5; VDC_V: 50; Value2: 50V; TaMin_C: -55; TaMax_C: 125; Cap_Case: 0402; SizeArea_mm2: 0.5; SizeAreaWB_mm2: 3; SizeX_mm: 1; SizeZ_mm: 0.6; AEC Category: Q200; Green_Lifecycle: Not Set; Green_REACh: Incomplete
signal-integrity model Cap
simulation model Cap
footprint 0402
footprint 0402M
footprint 0402L
footprint 0402S
pins: 1, 2

## 885012005056
designator C?  ValueDisplayed: 15pF  (hidden comment: 885012005056)
CAP, CERM, 15 pF, 50 V,+/- 5%, C0G/NP0, 0402; Manufacturer: Wurth Elektronik; Polarized: N; CompType: Capacitor; Value: 15pF; U/M: EA; Cap_F: 0.000000000015; Tolerance_%: 5; VDC_V: 50; Value2: 50V; TaMin_C: -55; TaMax_C: 125; Cap_Case: 0402; SizeArea_mm2: 0.5; SizeAreaWB_mm2: 3; SizeX_mm: 1; SizeZ_mm: 0.6; AEC Category: Q200
signal-integrity model Cap
simulation model Cap
footprint 0402
footprint 0402M
footprint 0402L
footprint 0402S
pins: 1, 2

## 885012005061
designator C?  ValueDisplayed: 100pF  (hidden comment: 885012005061)
CAP, CERM, 100 pF, 50 V,+/- 5%, C0G/NP0, 0402; Manufacturer: Wurth Elektronik; Polarized: N; CompType: Capacitor; Value: 100pF; U/M: EA; Cap_F: 0.0000000001; Tolerance_%: 5; VDC_V: 50; Value2: 50V; TaMin_C: -55; TaMax_C: 125; Cap_Case: 0402; SizeArea_mm2: 0.5; SizeAreaWB_mm2: 3; SizeX_mm: 1; SizeZ_mm: 0.6; AEC Category: Q200; Green_Lifecycle: Not Set; Green_REACh: Incomplete
signal-integrity model Cap
simulation model Cap
footprint 0402
footprint 0402M
footprint 0402L
footprint 0402S
pins: 1, 2

## 885012005062
designator C?  ValueDisplayed: 150pF  (hidden comment: 885012005062)
CAP, CERM, 150 pF, 50 V,+/- 5%, C0G/NP0, 0402; Manufacturer: Wurth Elektronik; Polarized: N; CompType: Capacitor; Value: 150pF; U/M: EA; Cap_F: 0.00000000015; Tolerance_%: 5; VDC_V: 50; Value2: 50V; TaMin_C: -55; TaMax_C: 125; Cap_Case: 0402; SizeArea_mm2: 0.5; SizeAreaWB_mm2: 3; SizeX_mm: 1; SizeZ_mm: 0.6; AEC Category: Q200
signal-integrity model Cap
simulation model Cap
footprint 0402
footprint 0402M
footprint 0402L
footprint 0402S
pins: 1, 2

## 885012005063
designator C?  ValueDisplayed: 220pF  (hidden comment: 885012005063)
CAP, CERM, 220 pF, 50 V,+/- 5%, C0G/NP0, 0402; Manufacturer: Wurth Elektronik; Polarized: N; CompType: Capacitor; Value: 220pF; U/M: EA; Cap_F: 0.00000000022; Tolerance_%: 5; VDC_V: 50; Value2: 50V; TaMin_C: -55; TaMax_C: 125; Cap_Case: 0402; SizeArea_mm2: 0.5; SizeAreaWB_mm2: 3; SizeX_mm: 1; SizeZ_mm: 0.6; AEC Category: Q200; Green_Lifecycle: Not Set; Green_REACh: Incomplete
signal-integrity model Cap
simulation model Cap
footprint 0402
footprint 0402M
footprint 0402L
footprint 0402S
pins: 1, 2

## 885012006052
designator C?  ValueDisplayed: 15pF  (hidden comment: 885012006052)
CAP, CERM, 15 pF, 50 V,+/- 5%, C0G/NP0, 0603; Manufacturer: Wurth Elektronik; Polarized: N; CompType: Capacitor; Value: 15pF; U/M: EA; Cap_F: 0.000000000015; Tolerance_%: 5; VDC_V: 50; Value2: 50V; TaMin_C: -55; TaMax_C: 125; Cap_Case: 0603; SizeArea_mm2: 1.28; SizeAreaWB_mm2: 4.68; SizeX_mm: 1.6; SizeY_mm: 0.8; SizeZ_mm: 1; AEC Category: Q200; Green_Lifecycle: Not Set; Green_REACh: Incomplete
signal-integrity model Cap
simulation model Cap
footprint 0603
footprint 0603M
footprint 0603L
footprint 0603_HV
footprint 0603S
pins: 1, 2

## 885012006057
designator C?  ValueDisplayed: 100pF  (hidden comment: 885012006057)
CAP, CERM, 100 pF, 50 V,+/- 5%, C0G/NP0, 0603; Manufacturer: Wurth Elektronik; Polarized: N; CompType: Capacitor; Value: 100pF; U/M: EA; Cap_F: 0.0000000001; Tolerance_%: 5; VDC_V: 50; Value2: 50V; TaMin_C: -55; TaMax_C: 125; Cap_Case: 0603; SizeArea_mm2: 1.28; SizeAreaWB_mm2: 4.68; SizeX_mm: 1.6; SizeY_mm: 0.8; SizeZ_mm: 1; AEC Category: Q200
signal-integrity model Cap
simulation model Cap
footprint 0603
footprint 0603M
footprint 0603L
footprint 0603_HV
footprint 0603S
pins: 1, 2

## 885012006060
designator C?  ValueDisplayed: 330pF  (hidden comment: 885012006060)
CAP, CERM, 330 pF, 50 V,+/- 5%, C0G/NP0, 0603; Manufacturer: Wurth Elektronik; Polarized: N; CompType: Capacitor; Value: 330pF; U/M: EA; Cap_F: 0.00000000033; Tolerance_%: 5; VDC_V: 50; Value2: 50V; TaMin_C: -55; TaMax_C: 125; Cap_Case: 0603; SizeArea_mm2: 1.28; SizeAreaWB_mm2: 4.68; SizeX_mm: 1.6; SizeY_mm: 0.8; SizeZ_mm: 1; AEC Category: Q200
signal-integrity model Cap
simulation model Cap
footprint 0603
footprint 0603M
footprint 0603L
footprint 0603_HV
footprint 0603S
pins: 1, 2

## 885012105001
designator C?  ValueDisplayed: 0.1µF  (hidden comment: 885012105001)
CAP, CERM, 0.1 µF, 6.3 V,+/- 20%, X5R, 0402; Manufacturer: Wurth Elektronik; Polarized: N; CompType: Capacitor; Value: 0.1uF; U/M: EA; Cap_F: 0.0000001; Tolerance_%: 20; VDC_V: 6.3; Value2: 6.3V; TaMin_C: -55; TaMax_C: 85; Cap_Case: 0402; SizeArea_mm2: 0.5; SizeAreaWB_mm2: 3; SizeX_mm: 1; SizeZ_mm: 0.6; AEC Category: Q200; Green_Lifecycle: Active; Green_REACh: Passed
signal-integrity model Cap
simulation model Cap
footprint 0402
footprint 0402M
footprint 0402L
footprint 0402S
pins: 1, 2

## 885012105008
designator C?  ValueDisplayed: 4.7µF  (hidden comment: 885012105008)
CAP, CERM, 4.7 µF, 6.3 V,+/- 20%, X5R, 0402; Manufacturer: Wurth Elektronik; Polarized: N; CompType: Capacitor; Value: 4.7uF; U/M: EA; Cap_F: 0.0000047; Tolerance_%: 20; VDC_V: 6.3; Value2: 6.3V; TaMin_C: -55; TaMax_C: 85; Cap_Case: 0402; SizeArea_mm2: 0.5; SizeAreaWB_mm2: 3; SizeX_mm: 1; SizeZ_mm: 0.6; AEC Category: Q200; Green_Lifecycle: Not Set; Green_REACh: Incomplete
signal-integrity model Cap
simulation model Cap
footprint 0402
footprint 0402M
footprint 0402L
footprint 0402S
pins: 1, 2

## 885012105010
designator C?  ValueDisplayed: 0.1µF  (hidden comment: 885012105010)
CAP, CERM, 0.1 µF, 10 V,+/- 20%, X5R, 0402; Manufacturer: Wurth Elektronik; Polarized: N; CompType: Capacitor; Value: 0.1uF; U/M: EA; Cap_F: 0.0000001; Tolerance_%: 20; VDC_V: 10; Value2: 10V; TaMin_C: -55; TaMax_C: 85; Cap_Case: 0402; SizeArea_mm2: 0.5; SizeAreaWB_mm2: 3; SizeX_mm: 1; SizeZ_mm: 0.6; AEC Category: Q200; Green_Lifecycle: Not Set; Green_REACh: Incomplete
signal-integrity model Cap
simulation model Cap
footprint 0402
footprint 0402M
footprint 0402L
footprint 0402S
pins: 1, 2

## 885012105012
designator C?  ValueDisplayed: 1µF  (hidden comment: 885012105012)
CAP, CERM, 1 µF, 10 V,+/- 20%, X5R, 0402; Manufacturer: Wurth Elektronik; Polarized: N; CompType: Capacitor; Value: 1uF; U/M: EA; Cap_F: 0.000001; Tolerance_%: 20; VDC_V: 10; Value2: 10V; TaMin_C: -55; TaMax_C: 85; Cap_Case: 0402; SizeArea_mm2: 0.5; SizeAreaWB_mm2: 3; SizeX_mm: 1; SizeZ_mm: 0.6; AEC Category: Q200
signal-integrity model Cap
simulation model Cap
footprint 0402
footprint 0402M
footprint 0402L
footprint 0402S
pins: 1, 2

## 885012105013
designator C?  ValueDisplayed: 2.2µF  (hidden comment: 885012105013)
CAP, CERM, 2.2 µF, 10 V,+/- 20%, X5R, 0402; Manufacturer: Wurth Elektronik; Polarized: N; CompType: Capacitor; Value: 2.2uF; U/M: EA; Cap_F: 0.0000022; Tolerance_%: 20; VDC_V: 10; Value2: 10V; TaMin_C: -55; TaMax_C: 85; Cap_Case: 0402; SizeArea_mm2: 0.5; SizeAreaWB_mm2: 3; SizeX_mm: 1; SizeZ_mm: 0.6; AEC Category: Q200
signal-integrity model Cap
simulation model Cap
footprint 0402
footprint 0402M
footprint 0402L
footprint 0402S
pins: 1, 2

## 885012105016
designator C?  ValueDisplayed: 0.1µF  (hidden comment: 885012105016)
CAP, CERM, 0.1 µF, 16 V,+/- 20%, X5R, 0402; Manufacturer: Wurth Elektronik; Polarized: N; CompType: Capacitor; Value: 0.1uF; U/M: EA; Cap_F: 0.0000001; Tolerance_%: 20; VDC_V: 16; Value2: 16V; TaMin_C: -55; TaMax_C: 85; Cap_Case: 0402; SizeArea_mm2: 0.5; SizeAreaWB_mm2: 3; SizeX_mm: 1; SizeZ_mm: 0.6; AEC Category: Q200
signal-integrity model Cap
simulation model Cap
footprint 0402
footprint 0402M
footprint 0402L
footprint 0402S
pins: 1, 2

## 885012106017
designator C?  ValueDisplayed: 1µF  (hidden comment: 885012106017)
CAP, CERM, 1 µF, 16 V,+/- 20%, X5R, 0603; Manufacturer: Wurth Elektronik; Polarized: N; CompType: Capacitor; Value: 1uF; U/M: EA; Cap_F: 0.000001; Tolerance_%: 20; VDC_V: 16; Value2: 16V; TaMin_C: -55; TaMax_C: 85; Cap_Case: 0603; SizeArea_mm2: 1.28; SizeAreaWB_mm2: 4.68; SizeX_mm: 1.6; SizeY_mm: 0.8; SizeZ_mm: 1; AEC Category: Q200
signal-integrity model Cap
simulation model Cap
footprint 0603
footprint 0603M
footprint 0603L
footprint 0603_HV
footprint 0603S
pins: 1, 2

## 885012106018
designator C?  ValueDisplayed: 2.2µF  (hidden comment: 885012106018)
CAP, CERM, 2.2 µF, 16 V,+/- 20%, X5R, 0603; Manufacturer: Wurth Elektronik; Polarized: N; CompType: Capacitor; Value: 2.2uF; U/M: EA; Cap_F: 0.0000022; Tolerance_%: 20; VDC_V: 16; Value2: 16V; TaMin_C: -55; TaMax_C: 85; Cap_Case: 0603; SizeArea_mm2: 1.28; SizeAreaWB_mm2: 4.68; SizeX_mm: 1.6; SizeY_mm: 0.8; SizeZ_mm: 1; AEC Category: Q200; Green_Lifecycle: Not Set; Green_REACh: Incomplete
signal-integrity model Cap
simulation model Cap
footprint 0603
footprint 0603M
footprint 0603L
footprint 0603_HV
footprint 0603S
pins: 1, 2

## 885012107013
designator C?  ValueDisplayed: 4.7µF  (hidden comment: 885012107013)
CAP, CERM, 4.7 µF, 16 V,+/- 20%, X5R, 0805; Manufacturer: Wurth Elektronik; Polarized: N; CompType: Capacitor; Value: 4.7uF; U/M: EA; Cap_F: 0.0000047; Tolerance_%: 20; VDC_V: 16; Value2: 16V; TaMin_C: -55; TaMax_C: 85; Cap_Case: 0805; SizeArea_mm2: 2.5; SizeAreaWB_mm2: 6.75; SizeX_mm: 2; SizeY_mm: 1.25; SizeZ_mm: 1.45; AEC Category: Q200
signal-integrity model Cap
simulation model Cap
footprint 0805_HV
footprint 0805_HV1
footprint 0805
footprint 0805M
footprint 0805L
pins: 1, 2

## 885012205008
designator C?  ValueDisplayed: 2200pF  (hidden comment: 885012205008)
CAP, CERM, 2200 pF, 10 V,+/- 10%, X7R, 0402; Manufacturer: Wurth Elektronik; Polarized: N; CompType: Capacitor; Value: 2200pF; U/M: EA; Cap_F: 0.0000000022; Tolerance_%: 10; Value2: 10V; TaMin_C: -55; TaMax_C: 125; Cap_Case: 0402; SizeArea_mm2: 0.5; SizeAreaWB_mm2: 3; SizeX_mm: 1; SizeZ_mm: 0.6; AEC Category: Q200; Green_Lifecycle: Not Set; Green_REACh: Incomplete
signal-integrity model Cap
simulation model Cap
footprint 0402
footprint 0402M
footprint 0402L
footprint 0402S
pins: 1, 2

## 885012205027
designator C?  ValueDisplayed: 2200pF  (hidden comment: 885012205027)
CAP, CERM, 2200 pF, 16 V,+/- 10%, X7R, 0402; Manufacturer: Wurth Elektronik; Polarized: N; CompType: Capacitor; Value: 2200pF; U/M: EA; Cap_F: 0.0000000022; Tolerance_%: 10; VDC_V: 16; Value2: 16V; TaMin_C: -55; TaMax_C: 125; Cap_Case: 0402; SizeArea_mm2: 0.5; SizeAreaWB_mm2: 3; SizeX_mm: 1; SizeZ_mm: 0.6; AEC Category: Q200
signal-integrity model Cap
simulation model Cap
footprint 0402
footprint 0402M
footprint 0402L
footprint 0402S
pins: 1, 2

## 885012205029
designator C?  ValueDisplayed: 4700pF  (hidden comment: 885012205029)
CAP, CERM, 4700 pF, 16 V,+/- 10%, X7R, 0402; Manufacturer: Wurth Elektronik; Polarized: N; CompType: Capacitor; Value: 4700pF; U/M: EA; Cap_F: 0.0000000047; Tolerance_%: 10; VDC_V: 16; Value2: 16V; TaMin_C: -55; TaMax_C: 125; Cap_Case: 0402; SizeArea_mm2: 0.5; SizeAreaWB_mm2: 3; SizeX_mm: 1; SizeZ_mm: 0.6; AEC Category: Q200; Green_Lifecycle: Not Set; Green_REACh: Incomplete
signal-integrity model Cap
simulation model Cap
footprint 0402
footprint 0402M
footprint 0402L
footprint 0402S
pins: 1, 2

## 885012205031
designator C?  ValueDisplayed: 0.01µF  (hidden comment: 885012205031)
CAP, CERM, 0.01 µF, 16 V,+/- 10%, X7R, 0402; Manufacturer: Wurth Elektronik; Polarized: N; CompType: Capacitor; Value: 0.01uF; U/M: EA; Cap_F: 0.00000001; Tolerance_%: 10; VDC_V: 16; Value2: 16V; TaMin_C: -55; TaMax_C: 125; Cap_Case: 0402; SizeArea_mm2: 0.5; SizeAreaWB_mm2: 3; SizeX_mm: 1; SizeZ_mm: 0.6; AEC Category: Q200; Green_Lifecycle: Active; Green_REACh: Passed
signal-integrity model Cap
simulation model Cap
footprint 0402
footprint 0402M
footprint 0402L
footprint 0402S
pins: 1, 2

## 885012205037
designator C?  ValueDisplayed: 0.1µF  (hidden comment: 885012205037)
CAP, CERM, 0.1 µF, 16 V,+/- 10%, X7R, 0402; Manufacturer: Wurth Elektronik; Polarized: N; CompType: Capacitor; Value: 0.1uF; U/M: EA; Cap_F: 0.0000001; Tolerance_%: 10; VDC_V: 16; Value2: 16V; TaMin_C: -55; TaMax_C: 125; Cap_Case: 0402; SizeArea_mm2: 0.5; SizeAreaWB_mm2: 3; SizeX_mm: 1; SizeZ_mm: 0.6; AEC Category: Q200; Green_Lifecycle: Active; Green_REACh: Passed
signal-integrity model Cap
simulation model Cap
footprint 0402
footprint 0402M
footprint 0402L
footprint 0402S
pins: 1, 2

## 885012205044
designator C?  ValueDisplayed: 1000pF  (hidden comment: 885012205044)
CAP, CERM, 1000 pF, 25 V,+/- 10%, X7R, 0402; Manufacturer: Wurth Elektronik; Polarized: N; CompType: Capacitor; Value: 1000pF; U/M: EA; Cap_F: 0.000000001; Tolerance_%: 10; VDC_V: 25; Value2: 25V; TaMin_C: -55; TaMax_C: 125; Cap_Case: 0402; SizeArea_mm2: 0.5; SizeAreaWB_mm2: 3; SizeX_mm: 1; SizeZ_mm: 0.6; AEC Category: Q200
signal-integrity model Cap
simulation model Cap
footprint 0402
footprint 0402M
footprint 0402L
footprint 0402S
pins: 1, 2

## 885012205055
designator C?  ValueDisplayed: 100pF  (hidden comment: 885012205055)
CAP, CERM, 100 pF, 50 V,+/- 10%, X7R, 0402; Manufacturer: Wurth Elektronik; Polarized: N; CompType: Capacitor; Value: 100pF; U/M: EA; Cap_F: 0.0000000001; Tolerance_%: 10; VDC_V: 50; Value2: 50V; TaMin_C: -55; TaMax_C: 125; Cap_Case: 0402; SizeArea_mm2: 0.5; SizeAreaWB_mm2: 3; SizeX_mm: 1; SizeZ_mm: 0.6; AEC Category: Q200; Green_Lifecycle: Not Set; Green_REACh: Incomplete
signal-integrity model Cap
simulation model Cap
footprint 0402
footprint 0402M
footprint 0402L
footprint 0402S
pins: 1, 2

## 885012205061
designator C?  ValueDisplayed: 1000pF  (hidden comment: 885012205061)
CAP, CERM, 1000 pF, 50 V,+/- 10%, X7R, 0402; Manufacturer: Wurth Elektronik; Polarized: N; CompType: Capacitor; Value: 1000pF; U/M: EA; Cap_F: 0.000000001; Tolerance_%: 10; VDC_V: 50; Value2: 50V; TaMin_C: -55; TaMax_C: 125; Cap_Case: 0402; SizeArea_mm2: 0.5; SizeAreaWB_mm2: 3; SizeX_mm: 1; SizeZ_mm: 0.6; AEC Category: Q200; Green_Lifecycle: Not Set; Green_REACh: Incomplete
signal-integrity model Cap
simulation model Cap
footprint 0402
footprint 0402M
footprint 0402L
footprint 0402S
pins: 1, 2

## 885012206020
designator C?  ValueDisplayed: 0.1µF  (hidden comment: 885012206020)
CAP, CERM, 0.1 µF, 10 V,+/- 10%, X7R, 0603; Manufacturer: Wurth Elektronik; Polarized: N; CompType: Capacitor; Value: 0.1uF; U/M: EA; Cap_F: 0.0000001; Tolerance_%: 10; Value2: 10V; TaMin_C: -55; TaMax_C: 125; Cap_Case: 0603; SizeArea_mm2: 1.28; SizeAreaWB_mm2: 4.68; SizeX_mm: 1.6; SizeY_mm: 0.8; SizeZ_mm: 1; AEC Category: Q200
signal-integrity model Cap
simulation model Cap
footprint 0603
footprint 0603M
footprint 0603L
footprint 0603_HV
footprint 0603S
pins: 1, 2

## 885012206022
designator C?  ValueDisplayed: 0.22µF  (hidden comment: 885012206022)
CAP, CERM, 0.22 µF, 10 V,+/- 10%, X7R, 0603; Manufacturer: Wurth Elektronik; Polarized: N; CompType: Capacitor; Value: 0.22uF; U/M: EA; Cap_F: 0.00000022; Tolerance_%: 10; Value2: 10V; TaMin_C: -55; TaMax_C: 125; Cap_Case: 0603; SizeArea_mm2: 1.28; SizeAreaWB_mm2: 4.68; SizeX_mm: 1.6; SizeY_mm: 0.8; SizeZ_mm: 1; AEC Category: Q200
signal-integrity model Cap
simulation model Cap
footprint 0603
footprint 0603M
footprint 0603L
footprint 0603_HV
footprint 0603S
pins: 1, 2

## 885012206026
designator C?  ValueDisplayed: 1µF  (hidden comment: 885012206026)
CAP, CERM, 1 µF, 10 V,+/- 10%, X7R, 0603; Manufacturer: Wurth Elektronik; Polarized: N; CompType: Capacitor; Value: 1uF; U/M: EA; Cap_F: 0.000001; Tolerance_%: 10; Value2: 10V; TaMin_C: -55; TaMax_C: 125; Cap_Case: 0603; SizeArea_mm2: 1.28; SizeAreaWB_mm2: 4.68; SizeX_mm: 1.6; SizeY_mm: 0.8; SizeZ_mm: 1; AEC Category: Q200
signal-integrity model Cap
simulation model Cap
footprint 0603
footprint 0603M
footprint 0603L
footprint 0603_HV
footprint 0603S
pins: 1, 2

## 885012206034
designator C?  ValueDisplayed: 1000pF  (hidden comment: 885012206034)
CAP, CERM, 1000 pF, 16 V,+/- 10%, X7R, 0603; Manufacturer: Wurth Elektronik; Polarized: N; CompType: Capacitor; Value: 1000pF; U/M: EA; Cap_F: 0.000000001; Tolerance_%: 10; VDC_V: 16; Value2: 16V; TaMin_C: -55; TaMax_C: 125; Cap_Case: 0603; SizeArea_mm2: 1.28; SizeAreaWB_mm2: 4.68; SizeX_mm: 1.6; SizeY_mm: 0.8; SizeZ_mm: 1; AEC Category: Q200
signal-integrity model Cap
simulation model Cap
footprint 0603
footprint 0603M
footprint 0603L
footprint 0603_HV
footprint 0603S
pins: 1, 2

## 885012206036
designator C?  ValueDisplayed: 2200pF  (hidden comment: 885012206036)
CAP, CERM, 2200 pF, 16 V,+/- 10%, X7R, 0603; Manufacturer: Wurth Elektronik; Polarized: N; CompType: Capacitor; Value: 2200pF; U/M: EA; Cap_F: 0.0000000022; Tolerance_%: 10; VDC_V: 16; Value2: 16V; TaMin_C: -55; TaMax_C: 125; Cap_Case: 0603; SizeArea_mm2: 1.28; SizeAreaWB_mm2: 4.68; SizeX_mm: 1.6; SizeY_mm: 0.8; SizeZ_mm: 1; AEC Category: Q200
signal-integrity model Cap
simulation model Cap
footprint 0603
footprint 0603M
footprint 0603L
footprint 0603_HV
footprint 0603S
pins: 1, 2

## 885012206040
designator C?  ValueDisplayed: 0.01µF  (hidden comment: 885012206040)
CAP, CERM, 0.01 µF, 16 V,+/- 10%, X7R, 0603; Manufacturer: Wurth Elektronik; Polarized: N; CompType: Capacitor; Value: 0.01uF; U/M: EA; Cap_F: 0.00000001; Tolerance_%: 10; VDC_V: 16; Value2: 16V; TaMin_C: -55; TaMax_C: 125; Cap_Case: 0603; SizeArea_mm2: 1.28; SizeAreaWB_mm2: 4.68; SizeX_mm: 1.6; SizeY_mm: 0.8; SizeZ_mm: 1; AEC Category: Q200; Green_Lifecycle: Active; Green_REACh: Passed
signal-integrity model Cap
simulation model Cap
footprint 0603
footprint 0603M
footprint 0603L
footprint 0603_HV
footprint 0603S
pins: 1, 2

## 885012206046
designator C?  ValueDisplayed: 0.1µF  (hidden comment: 885012206046)
CAP, CERM, 0.1 µF, 16 V,+/- 10%, X7R, 0603; Manufacturer: Wurth Elektronik; Polarized: N; CompType: Capacitor; Value: 0.1uF; U/M: EA; Cap_F: 0.0000001; Tolerance_%: 10; VDC_V: 16; Value2: 16V; TaMin_C: -55; TaMax_C: 125; Cap_Case: 0603; SizeArea_mm2: 1.28; SizeAreaWB_mm2: 4.68; SizeX_mm: 1.6; SizeY_mm: 0.8; SizeZ_mm: 1; AEC Category: Q200
signal-integrity model Cap
simulation model Cap
footprint 0603
footprint 0603M
footprint 0603L
footprint 0603_HV
footprint 0603S
pins: 1, 2

## 885012206048
designator C?  ValueDisplayed: 0.22µF  (hidden comment: 885012206048)
CAP, CERM, 0.22 µF, 16 V,+/- 10%, X7R, 0603; Manufacturer: Wurth Elektronik; Polarized: N; CompType: Capacitor; Value: 0.22uF; U/M: EA; Cap_F: 0.00000022; Tolerance_%: 10; VDC_V: 16; Value2: 16V; TaMin_C: -55; TaMax_C: 125; Cap_Case: 0603; SizeArea_mm2: 1.28; SizeAreaWB_mm2: 4.68; SizeX_mm: 1.6; SizeY_mm: 0.8; SizeZ_mm: 1; AEC Category: Q200
signal-integrity model Cap
simulation model Cap
footprint 0603
footprint 0603M
footprint 0603L
footprint 0603_HV
footprint 0603S
pins: 1, 2

## 885012206052
designator C?  ValueDisplayed: 1µF  (hidden comment: 885012206052)
CAP, CERM, 1 µF, 16 V,+/- 10%, X7R, 0603; Manufacturer: Wurth Elektronik; Polarized: N; CompType: Capacitor; Value: 1uF; U/M: EA; Cap_F: 0.000001; Tolerance_%: 10; VDC_V: 16; Value2: 16V; TaMin_C: -55; TaMax_C: 125; Cap_Case: 0603; SizeArea_mm2: 1.28; SizeAreaWB_mm2: 4.68; SizeX_mm: 1.6; SizeY_mm: 0.8; SizeZ_mm: 1; AEC Category: Q200; Green_Lifecycle: Active; Green_REACh: Passed
signal-integrity model Cap
simulation model Cap
footprint 0603
footprint 0603M
footprint 0603L
footprint 0603_HV
footprint 0603S
pins: 1, 2

## 885012206071
designator C?  ValueDisplayed: 0.1µF  (hidden comment: 885012206071)
CAP, CERM, 0.1 µF, 25 V,+/- 10%, X7R, 0603; Manufacturer: Wurth Elektronik; Polarized: N; CompType: Capacitor; Value: 0.1uF; U/M: EA; Cap_F: 0.0000001; Tolerance_%: 10; VDC_V: 25; Value2: 25V; TaMin_C: -55; TaMax_C: 125; Cap_Case: 0603; SizeArea_mm2: 1.28; SizeAreaWB_mm2: 4.68; SizeX_mm: 1.6; SizeY_mm: 0.8; SizeZ_mm: 1; AEC Category: Q200; Green_Lifecycle: Active; Green_REACh: Passed
signal-integrity model Cap
simulation model Cap
footprint 0603
footprint 0603M
footprint 0603L
footprint 0603_HV
footprint 0603S
pins: 1, 2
